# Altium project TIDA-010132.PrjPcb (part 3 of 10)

## Sheet AFE1-LMX2594.SchDoc
size 558 x 431 mm; Date: Not shown in title block; ApprovedBy: Not shown in title block; CheckedBy: Not shown in title block; Author: Not shown in title block; CompanyName: Not shown in title block; DrawnBy: Avinash N; Engineer: Not shown in title block; Organization: Not shown in title block; Address1: Not shown in title block; Address2: Not shown in title block; Address3: Not shown in title block; Address4: Not shown in title block; DocumentNumber: 1; Revision: Use project parameter SCH_Rev; SheetNumber: 5; SheetTotal: 32; PageSetup: Record=PageOptions¦CenterHorizontal=True¦CenterVertical=True¦PrintScale=1.00¦XCorrection=1.00¦YCorrection=1.00¦PrintKind=0¦BorderSize=5000000¦LeftOffset=0¦BottomOffset=0¦Orientation=2¦PaperLength=1000¦PaperWidth=1000¦Scale=100¦PaperSource=15¦PrintQuality=600¦MediaType=1¦DitherType=10¦PaperKind=Letter¦PrintScaleMode=1
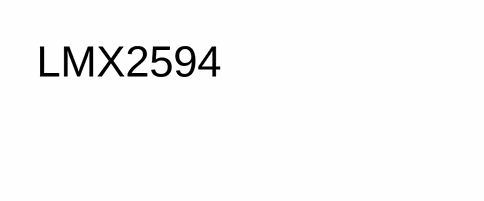
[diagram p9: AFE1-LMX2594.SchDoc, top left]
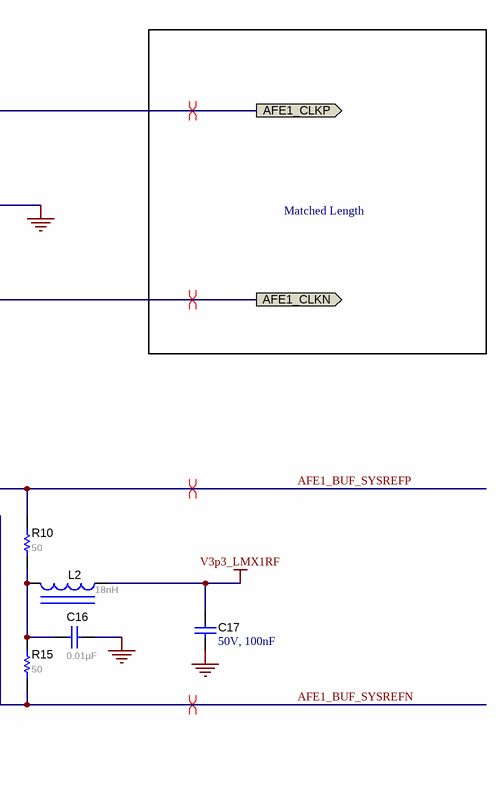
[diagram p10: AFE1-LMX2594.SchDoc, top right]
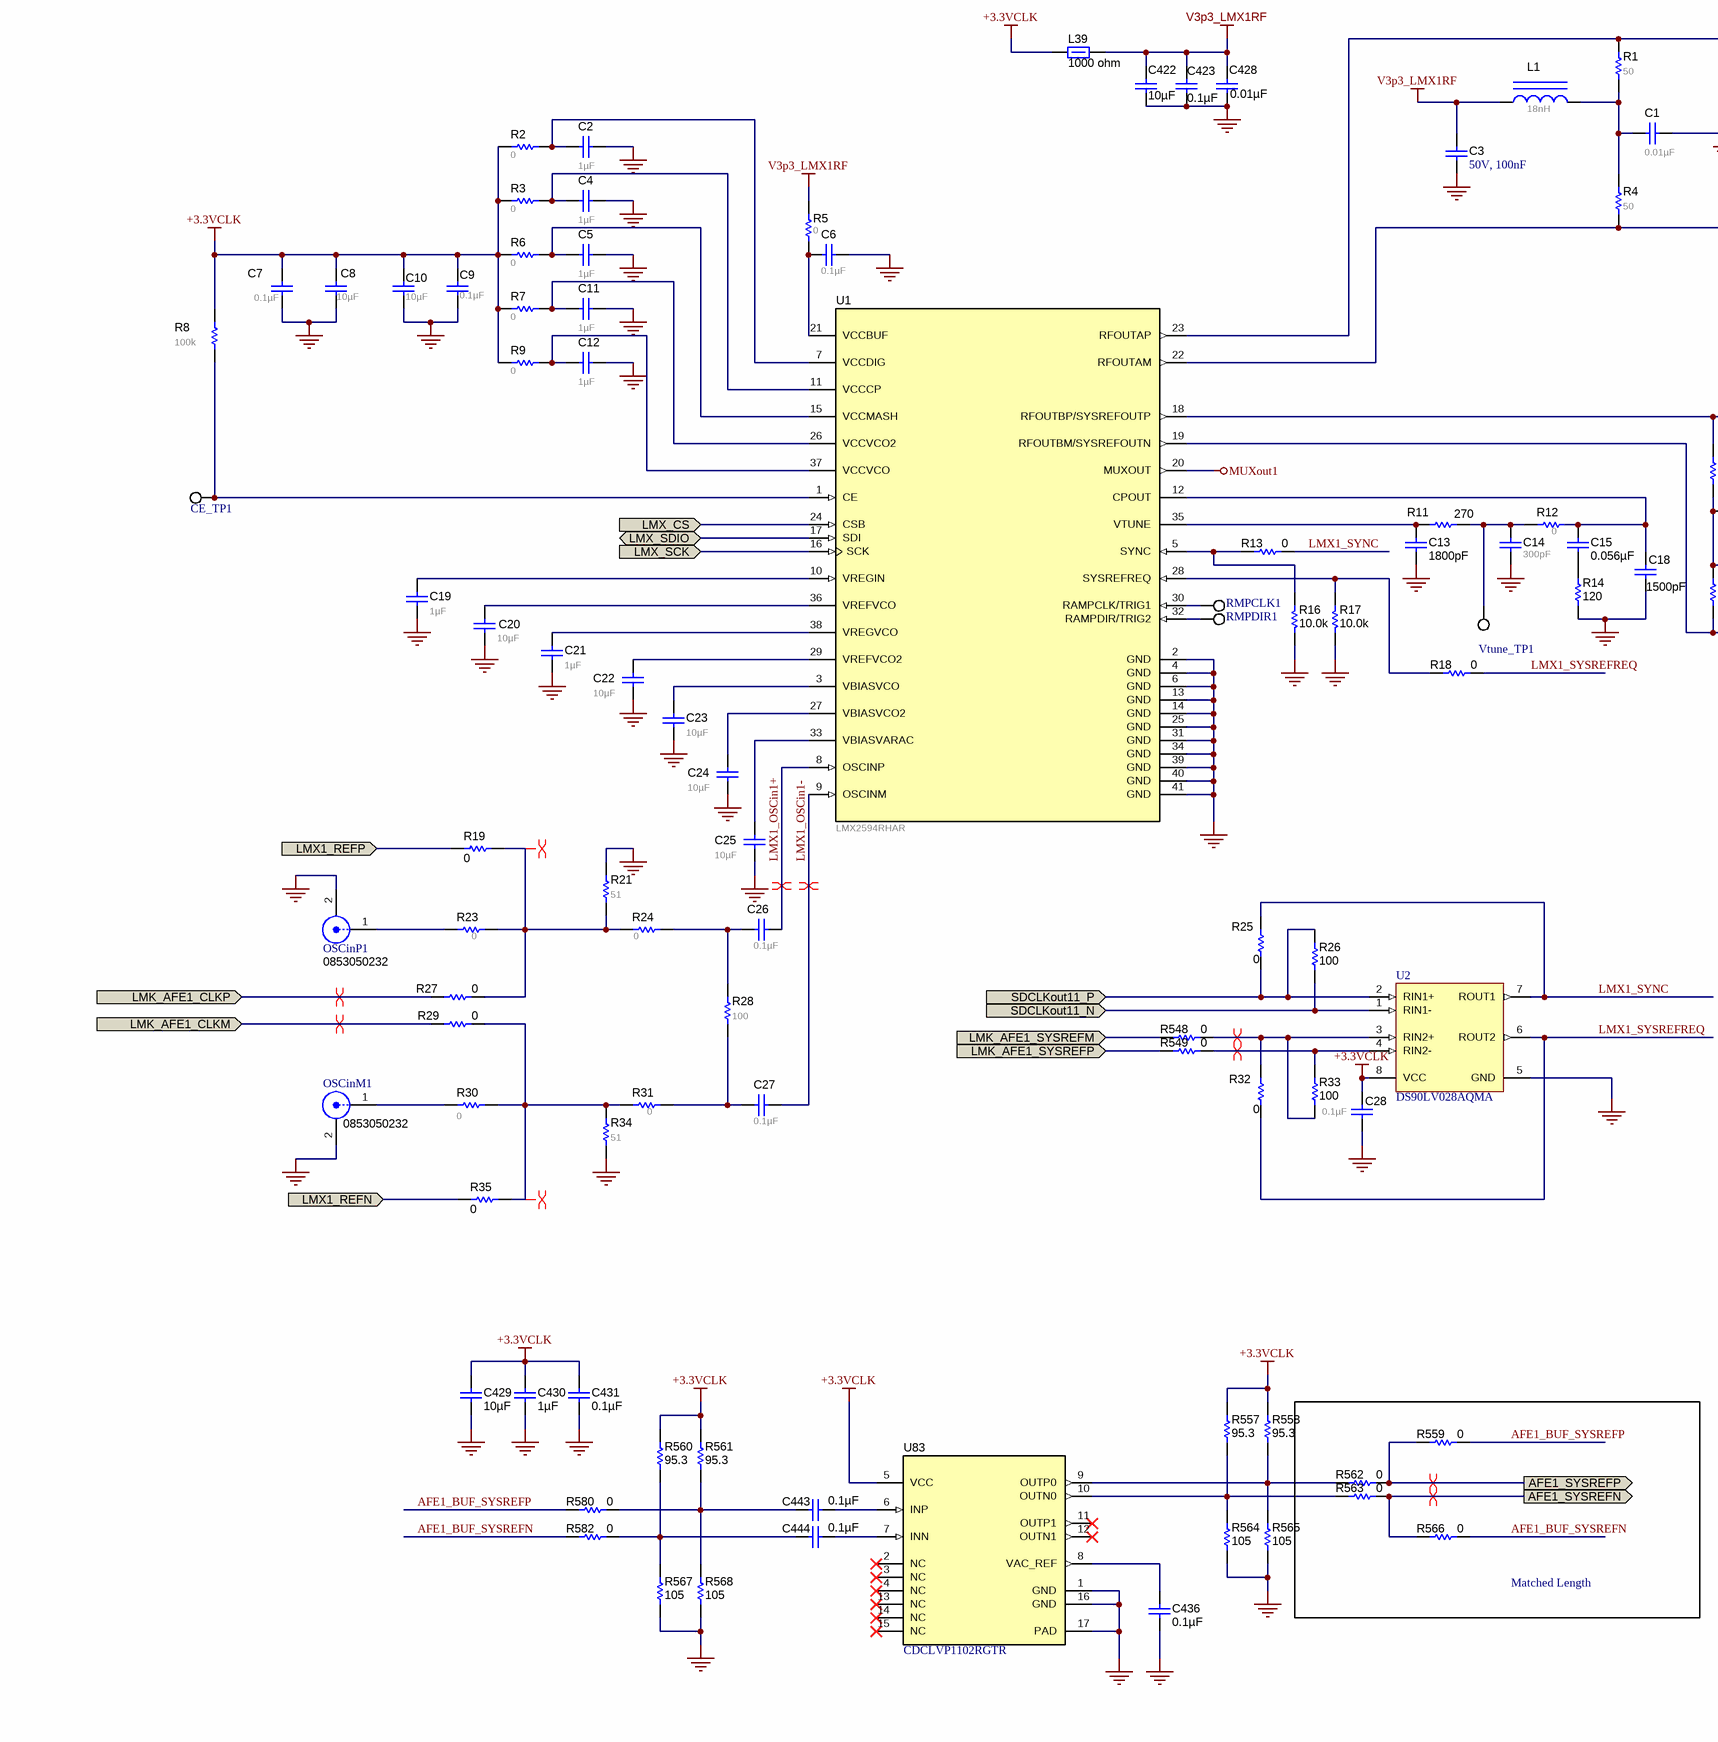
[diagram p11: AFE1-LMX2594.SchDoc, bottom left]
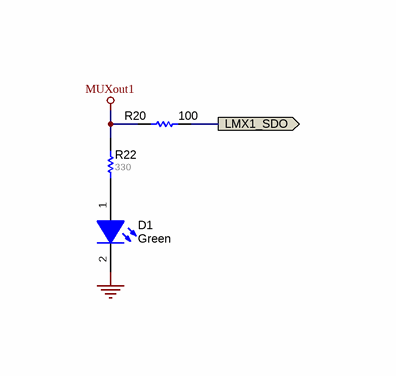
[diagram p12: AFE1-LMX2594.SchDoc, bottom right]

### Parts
C1  ValueDisplayed: 0.01µF  [0402_065]  (hidden comment: 520L103KT16T)
C2  ValueDisplayed: 1µF  [0603]  (hidden comment: C1608X7R1C105K080AC)
C3  50V, 100nF  [0603_1.6x0.8x0.8mm_Reflow Soldering]
C4  ValueDisplayed: 1µF  [0603L]  (hidden comment: C1608X7R1C105K080AC)
C5  ValueDisplayed: 1µF  [0603L]  (hidden comment: C1608X7R1C105K080AC)
C6  ValueDisplayed: 0.1µF  [0603L]  (hidden comment: 0603YC104JAT2A)
C7  ValueDisplayed: 0.1µF  [0603]  (hidden comment: 0603YC104JAT2A)
C8  ValueDisplayed: 10µF  [0805]  (hidden comment: C0805C106K8PACTU)
C9  ValueDisplayed: 0.1µF  [0603]  (hidden comment: 0603YC104JAT2A)
C10  ValueDisplayed: 10µF  [0805]  (hidden comment: C0805C106K8PACTU)
C11  ValueDisplayed: 1µF  [0603]  (hidden comment: C1608X7R1C105K080AC)
C12  ValueDisplayed: 1µF  [0603]  (hidden comment: C1608X7R1C105K080AC)
C13  ValueDisplayed: 1800pF  [0603]  (hidden comment: GRM1885C1H182JA01D)
C14  ValueDisplayed: 300pF  [0603]  (hidden comment: GRM1885C2A301JA01D)
C15  ValueDisplayed: 0.056µF  [0603]  (hidden comment: C0603C563J4RACTU)
C16  ValueDisplayed: 0.01µF  [0402_065]  (hidden comment: 520L103KT16T)
C17  50V, 100nF  [0603_1.6x0.8x0.8mm_Reflow Soldering]
C18  ValueDisplayed: 1500pF  [0603]  (hidden comment: 06031C152JAT2A)
C19  ValueDisplayed: 1µF  [0603]  (hidden comment: C1608X7R1C105K080AC)
C20  ValueDisplayed: 10µF  [0603]  (hidden comment: C1608X5R1A106M080AC)
C21  ValueDisplayed: 1µF  [0603]  (hidden comment: C1608X7R1C105K080AC)
C22  ValueDisplayed: 10µF  [0603]  (hidden comment: C1608X5R1A106M080AC)
C23  ValueDisplayed: 10µF  [0603]  (hidden comment: C1608X5R1A106M080AC)
C24  ValueDisplayed: 10µF  [0603]  (hidden comment: C1608X5R1A106M080AC)
C25  ValueDisplayed: 10µF  [0603]  (hidden comment: C1608X5R1A106M080AC)
C26  ValueDisplayed: 0.1µF  [0603L]  (hidden comment: 0603YC104JAT2A)
C27  ValueDisplayed: 0.1µF  [0603L]  (hidden comment: 0603YC104JAT2A)
C28  ValueDisplayed: 0.1µF  [0603]  (hidden comment: 0603YC104JAT2A)
C422  ValueDisplayed: 10µF  [1206_190]  (hidden comment: C3216X7R1E106M160AE)
C423  ValueDisplayed: 0.1µF  [0603]  (hidden comment: CGA3E2X7R1H104K080AA)
C428  ValueDisplayed: 0.01µF  [0603]  (hidden comment: GCM188R71H103KA37D)
C429  ValueDisplayed: 10µF  [0603]  (hidden comment: EMK107BBJ106MA-T)
C430  ValueDisplayed: 1µF  [0402]  (hidden comment: C1005X7S1A105K050BC)
C431  ValueDisplayed: 0.1µF  [0402]  (hidden comment: GRM155R71C104KA88D)
C436  ValueDisplayed: 0.1µF  [0402]  (hidden comment: GRM155R71C104KA88D)
C443  ValueDisplayed: 0.1µF  [0402]  (hidden comment: C1005X7R1E104M050BB)
C444  ValueDisplayed: 0.1µF  [0402]  (hidden comment: C1005X7R1E104M050BB)
CE_TP1  5002  [Keystone5002]  (value not drawn)
D1  value Green  [LTST-C191_Green]  (hidden comment: LTST-C191TGKT)
L1  ValueDisplayed: 18nH  [IND_LQG15H]  (hidden comment: LQG15HS18NJ02D)
L2  ValueDisplayed: 18nH  [IND_LQG15H]  (hidden comment: LQG15HS18NJ02D)
L39  ValueDisplayed: 1000 ohm  [1806_HighSpeed]  (hidden comment: BLM41PG102SN1L)
OSCinM1  0853050232  [Molex_0853050232]
OSCinP1  0853050232  [Molex_0853050232]
R1  ValueDisplayed: 50  [0402L]  (hidden comment: FC0402E50R0BST1)
R2  value 0  [0603]  (hidden comment: CRCW06030000Z0EA)
R3  value 0  [0603L]  (hidden comment: CRCW06030000Z0EA)
R4  ValueDisplayed: 50  [0402L]  (hidden comment: FC0402E50R0BST1)
R5  value 0  [0603L]  (hidden comment: CRCW06030000Z0EA)
R6  value 0  [0603L]  (hidden comment: CRCW06030000Z0EA)
R7  value 0  [0603]  (hidden comment: CRCW06030000Z0EA)
R8  ValueDisplayed: 100k  [0603]  (hidden comment: CRCW0603100KJNEA)
R9  value 0  [0603]  (hidden comment: CRCW06030000Z0EA)
R10  ValueDisplayed: 50  [0402L]  (hidden comment: FC0402E50R0BST1)
R11  ValueDisplayed: 270  [0603]  (hidden comment: RC0603JR-07270RL)
R12  ValueDisplayed: 0  [0603]  (hidden comment: CRCW06030000Z0EA)
R13  ValueDisplayed: 0  [0402]  (hidden comment: CRCW04020000Z0ED)
R14  ValueDisplayed: 120  [0603]  (hidden comment: RT0603DRE07120RL)
R15  ValueDisplayed: 50  [0402L]  (hidden comment: FC0402E50R0BST1)
R16  ValueDisplayed: 10.0k  [0402]  (hidden comment: CRCW040210K0DHEDP)
R17  ValueDisplayed: 10.0k  [0402]  (hidden comment: CRCW040210K0DHEDP)
R18  ValueDisplayed: 0  [0402]  (hidden comment: CRCW04020000Z0ED)
R19  ValueDisplayed: 0  [0402]  (hidden comment: CRCW04020000Z0ED)
R20  ValueDisplayed: 100  [0603]  (hidden comment: CRCW0603100RFKEA)
R21  ValueDisplayed: 51  [0603]  (hidden comment: CRCW060351R0JNEA)
R22  value 330  [0603]  (hidden comment: RC0603JR-07330RL)
R23  ValueDisplayed: 0  [0603]  (hidden comment: CRCW06030000Z0EA)
R24  ValueDisplayed: 0  [0603]  (hidden comment: CRCW06030000Z0EA)
R25  ValueDisplayed: 0  [0402]  (hidden comment: CRCW04020000Z0ED)
R26  ValueDisplayed: 100  [0402]  (hidden comment: CRCW0402100RJNED)
R27  ValueDisplayed: 0  [0402]  (hidden comment: CRCW04020000Z0ED)
R28  ValueDisplayed: 100  [0603L]  (hidden comment: CRCW0603100RFKEA)
R29  ValueDisplayed: 0  [0402]  (hidden comment: CRCW04020000Z0ED)
R30  ValueDisplayed: 0  [0603]  (hidden comment: CRCW06030000Z0EA)
R31  ValueDisplayed: 0  [0603]  (hidden comment: CRCW06030000Z0EA)
R32  ValueDisplayed: 0  [0402]  (hidden comment: CRCW04020000Z0ED)
R33  ValueDisplayed: 100  [0402]  (hidden comment: CRCW0402100RJNED)
R34  ValueDisplayed: 51  [0603]  (hidden comment: CRCW060351R0JNEA)
R35  ValueDisplayed: 0  [0402]  (hidden comment: CRCW04020000Z0ED)
R548  ValueDisplayed: 0  [0402]  (hidden comment: CRCW04020000Z0ED)
R549  ValueDisplayed: 0  [0402]  (hidden comment: CRCW04020000Z0ED)
R557  ValueDisplayed: 95.3  [0402]  (hidden comment: CRCW040295R3FKED)
R558  ValueDisplayed: 95.3  [0402]  (hidden comment: CRCW040295R3FKED)
R559  ValueDisplayed: 0  [0402]  (hidden comment: CRCW04020000Z0ED)
R560  ValueDisplayed: 95.3  [0402]  (hidden comment: CRCW040295R3FKED)
R561  ValueDisplayed: 95.3  [0402]  (hidden comment: CRCW040295R3FKED)
R562  ValueDisplayed: 0  [0402]  (hidden comment: CRCW04020000Z0ED)
R563  ValueDisplayed: 0  [0402]  (hidden comment: CRCW04020000Z0ED)
R564  ValueDisplayed: 105  [0402]  (hidden comment: CRCW0402105RFKED)
R565  ValueDisplayed: 105  [0402]  (hidden comment: CRCW0402105RFKED)
R566  ValueDisplayed: 0  [0402]  (hidden comment: CRCW04020000Z0ED)
R567  ValueDisplayed: 105  [0402]  (hidden comment: CRCW0402105RFKED)
R568  ValueDisplayed: 105  [0402]  (hidden comment: CRCW0402105RFKED)
R580  ValueDisplayed: 0  [0402]  (hidden comment: CRCW04020000Z0ED)
R582  ValueDisplayed: 0  [0402]  (hidden comment: CRCW04020000Z0ED)
RMPCLK1  5002  [Keystone5002]  (value not drawn)
RMPDIR1  5002  [Keystone5002]  (value not drawn)
U1  LMX2594RHAR  [RHA0040A]
U2  DS90LV028AQMA  [M08A_N]
U83  CDCLVP1102RGTR  [RGT0016B]
Vtune_TP1  5002  [Keystone5002]  (value not drawn)

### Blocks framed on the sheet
Matched Length: R559 R562 R563 R566

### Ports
AFE1_CLKN (out), AFE1_CLKP (out), AFE1_SYSREFN (out), AFE1_SYSREFP (out), LMK_AFE1_CLKM (in), LMK_AFE1_CLKP (in), LMK_AFE1_SYSREFM (in), LMK_AFE1_SYSREFP (in), LMX1_REFN (in), LMX1_REFP (in), LMX1_SDO (out), LMX_CS (in), LMX_SCK (in), LMX_SDIO (bidir), SDCLKout11_N (in), SDCLKout11_P (in)

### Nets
+3.3VCLK: C7.2 C8.2 C9.2 C10.2 C28.2 C429.1 C430.1 C431.1 L39.1 R2.1 R3.1 R6.1 R7.2 R8.1 R9.2 R557.2 R558.2 R560.2 R561.2 U2.8(VCC) U83.5(VCC)
GND: C1.1 C2.1 C3.2 C4.1 C5.2 C6.1 C7.1 C8.1 C9.1 C10.1 C11.1 C12.1 C13.1 C14.2 C16.1 C17.2 C18.2 C19.1 C20.2 C21.1 C22.2 C23.2 C24.1 C25.1 C28.1 C422.1 C423.2 C428.2 C429.2 C430.2 C431.2 C436.2 D1.2(K) OSCinM1.2 OSCinP1.2 R14.2 R16.2 R17.2 R21.2 R34.1 R564.1 R565.1 R567.1 R568.1 U1.2(GND) U1.4(GND) U1.6(GND) U1.13(GND) U1.14(GND) U1.25(GND) U1.31(GND) U1.34(GND) U1.39(GND) U1.40(GND) U1.41(GND) U2.5(GND) U83.1(GND) U83.16(GND) U83.17(PAD)
MUXout1: R20.1 R22.2 U1.20(MUXOUT)
V3p3_LMX1RF: C3.1 C17.1 C422.2 C423.1 C428.1 L1.1 L2.1 L39.2 R5.1
AFE1_BUF_SYSREFN: R15.1 R566.2 R582.1 U1.19(RFOUTBM/SYSREFOUTN)
AFE1_BUF_SYSREFP: R10.2 R559.2 R580.1 U1.18(RFOUTBP/SYSREFOUTP)
AFE1_CLKN: R4.1 U1.22(RFOUTAM) ; port AFE1_CLKN
AFE1_CLKP: R1.1 U1.23(RFOUTAP) ; port AFE1_CLKP
AFE1_SYSREFN: R563.2 R566.1 ; port AFE1_SYSREFN
AFE1_SYSREFP: R559.1 R562.2 ; port AFE1_SYSREFP
LMK_AFE1_CLKM: R29.1 ; port LMK_AFE1_CLKM
LMK_AFE1_CLKP: R27.1 ; port LMK_AFE1_CLKP
LMK_AFE1_SYSREFM: R548.1 ; port LMK_AFE1_SYSREFM
LMK_AFE1_SYSREFP: R549.1 ; port LMK_AFE1_SYSREFP
LMX1_OSCin1+: C26.2 U1.8(OSCINP)
LMX1_OSCin1-: C27.2 U1.9(OSCINM)
LMX1_REFN: R35.1 ; port LMX1_REFN
LMX1_REFP: R19.2 ; port LMX1_REFP
LMX1_SDO: R20.2 ; port LMX1_SDO
LMX1_SYNC: R13.2 R25.1 U2.7(ROUT1)
LMX1_SYSREFREQ: R18.2 R32.2 U2.6(ROUT2)
LMX_CS: U1.24(CSB) ; port LMX_CS
LMX_SCK: U1.16(SCK) ; port LMX_SCK
LMX_SDIO: U1.17(SDI) ; port LMX_SDIO
SDCLKout11_N: R26.1 U2.1(RIN1-) ; port SDCLKout11_N
SDCLKout11_P: R25.2 R26.2 U2.2(RIN1+) ; port SDCLKout11_P
NetC1_2: C1.2 L1.2 R1.2 R4.2
NetC2_2: C2.2 R2.2 U1.7(VCCDIG)
NetC4_2: C4.2 R3.2 U1.11(VCCCP)
NetC5_1: C5.1 R6.2 U1.15(VCCMASH)
NetC6_2: C6.2 R5.2 U1.21(VCCBUF)
NetC11_2: C11.2 R7.1 U1.26(VCCVCO2)
NetC12_2: C12.2 R9.1 U1.37(VCCVCO)
NetC13_2: C13.2 R11.1 U1.35(VTUNE)
NetC14_1: C14.1 R11.2 R12.2 Vtune_TP1.1
NetC15_1: C15.1 C18.1 R12.1 U1.12(CPOUT)
NetC15_2: C15.2 R14.1
NetC16_2: C16.2 L2.2 R10.1 R15.2
NetC19_2: C19.2 U1.10(VREGIN)
NetC20_1: C20.1 U1.36(VREFVCO)
NetC21_2: C21.2 U1.38(VREGVCO)
NetC22_1: C22.1 U1.29(VREFVCO2)
NetC23_1: C23.1 U1.3(VBIASVCO)
NetC24_2: C24.2 U1.27(VBIASVCO2)
NetC25_2: C25.2 U1.33(VBIASVARAC)
NetC26_1: C26.1 R24.2 R28.2
NetC27_1: C27.1 R28.1 R31.1
NetC436_1: C436.1 U83.8(VAC_REF)
NetC443_1: C443.1 R561.1 R568.2 R580.2
NetC443_2: C443.2 U83.6(INP)
NetC444_1: C444.1 R560.1 R567.2 R582.2
NetC444_2: C444.2 U83.7(INN)
NetCE_TP1_1: CE_TP1.1 R8.2 U1.1(CE)
NetD1_1: D1.1(A) R22.1
NetOSCinM1_1: OSCinM1.1 R30.1
NetOSCinP1_1: OSCinP1.1 R23.1
NetR13_1: R13.1 R16.1 U1.5(SYNC)
NetR17_1: R17.1 R18.1 U1.28(SYSREFREQ)
NetR19_1: R19.1 R21.1 R23.2 R24.1 R27.2
NetR29_2: R29.2 R30.2 R31.2 R34.2 R35.2
NetR32_1: R32.1 R33.1 R548.2 U2.3(RIN2+)
NetR33_2: R33.2 R549.2 U2.4(RIN2-)
NetR557_1: R557.1 R563.1 R564.2 U83.10(OUTN0)
NetR558_1: R558.1 R562.1 R565.2 U83.9(OUTP0)
NetRMPCLK1_1: RMPCLK1.1 U1.30(RAMPCLK/TRIG1)
NetRMPDIR1_1: RMPDIR1.1 U1.32(RAMPDIR/TRIG2)

Not connected (* = marked no-connect by the designer): U83 2(NC)* 3(NC)* 4(NC)* 11(OUTP1)* 12(OUTN1)* 13(NC)* 14(NC)* 15(NC)*

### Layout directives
differential pair: AFE1_BUF_SYSREFN, AFE1_BUF_SYSREFP, AFE1_CLKN, AFE1_CLKP, AFE1_SYSREFN, AFE1_SYSREFP, LMK_AFE1_CLKM, LMK_AFE1_CLKP, LMX1_OSCin1+, LMX1_OSCin1-, NetR19_1, NetR29_2, NetR32_1, NetR33_2

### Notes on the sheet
- LMX2594
- Matched Length

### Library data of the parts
C1 C16 = 520L103KT16T: CAP, CERM, 0.01 µF, 16 V, +/- 10%, X7R, 0402; Manufacturer: AT Ceramics; Polarized: N; CompType: Capacitor; Value: 0.01uF; U/M: EA; Cap_F: 0.00000001; Tolerance_%: 10; Value1: Unknown; VDC_V: 16; Value2: 16V; TaMin_C: -55; TaMax_C: 125; Cap_Case: 0402; AEC Category: Q200; SizeArea_mm2: 0.5; SizeAreaWB_mm2: 3; SizeX_mm: 1; SizeZ_mm: 0.65
C2 C11 C12 = C1608X7R1C105K080AC: CAP, CERM, 1 µF, 16 V, +/- 10%, X7R, 0603; Manufacturer: TDK; ESR_ohm: 0.0057; Polarized: N; TaMax_C: 125; TaMin_C: -55; Tolerance_%: 10; VDC_V: 16; Cap_F: 0.000001; CompType: Capacitor; Value: 1uF; Value1: 0.0057 ohm; Value2: 16V; U/M: EA; SizeArea_mm2: 1.28; SizeAreaWB_mm2: 4.68; SizeX_mm: 1.6; SizeY_mm: 0.8; SizeZ_mm: 1; AEC Category: Q200
C3 C17 = 885012206095: WCAP-CSGP Ceramic Capacitors, 0603, X7R, 50V, 100nF; Manufacturer: Wurth Electronics Inc.; Rated Voltage: 50V DC
C4 C5 = C1608X7R1C105K080AC: CAP, CERM, 1 µF, 16 V, +/- 10%, X7R, 0603; Manufacturer: TDK; Cap_Case: 0603; ESR_ohm: 0.0057; Polarized: N; TaMax_C: 125; TaMin_C: -55; Tolerance_%: 10; VDC_V: 16; Cap_F: 0.000001; CompType: Capacitor; Value: 1uF; Value1: 0.0057 ohm; Value2: 16V; U/M: EA; SizeArea_mm2: 1.28; SizeAreaWB_mm2: 4.68; SizeX_mm: 1.6; SizeY_mm: 0.8; SizeZ_mm: 1; AEC Category: Q200
C6 C26 C27 = 0603YC104JAT2A: CAP, CERM, 0.1uF, 16V, +/-5%, X7R, 0603; Manufacturer: AVX; Cap_Case: 0603; ESR_Ohm: 0.039; Polarized: N; TaMax_C: 125; TaMin_C: -55; Tolerance_%: 5; VDC_V: 16; Cap_F: 0.0000001; CompType: Capacitor; Value1: 0.039 ohm; U/M: EA
C7 C9 C28 = 0603YC104JAT2A: CAP, CERM, 0.1uF, 16V, +/-5%, X7R, 0603; Manufacturer: AVX; ESR_Ohm: 0.039; Polarized: N; TaMax_C: 125; TaMin_C: -55; Tolerance_%: 5; VDC_V: 16; Cap_F: 0.0000001; CompType: Capacitor; Value1: 0.039 ohm; U/M: EA
C8 C10 = C0805C106K8PACTU: CAP, CERM, 10uF, 10V, +/-10%, X5R, 0805; Manufacturer: Kemet; ESR_Ohm: 0.003; IRMS_A: 11.43; Polarized: N; TaMax_C: 85; TaMin_C: -55; Tolerance_%: 10; Cap_F: 0.00001; CompType: Capacitor; U/M: EA; Value1: 0.003 ohm
C13 = GRM1885C1H182JA01D: CAP, CERM, 1800 pF, 50 V, +/- 5%, C0G/NP0, 0603; Manufacturer: MuRata; Polarized: N; TaMax_C: 125; TaMin_C: -55; Tolerance_%: 5; VDC_V: 50; Cap_F: 0.0000000018; CompType: Capacitor; Value: 1800pF; Value1: Unknown; Value2: 50V; U/M: EA; SizeArea_mm2: 1.28; SizeAreaWB_mm2: 4.68; SizeX_mm: 1.6; SizeY_mm: 0.8; SizeZ_mm: 1; AEC Category: Q200
C14 = GRM1885C2A301JA01D: CAP, CERM, 300pF, 100V, +/-5%, C0G/NP0, 0603; Manufacturer: MuRata; Polarized: N; TaMax_C: 125; TaMin_C: -55; Tolerance_%: 5; VDC_V: 100; Cap_F: 0.0000000003; CompType: Capacitor; Value1: Unknown; U/M: EA
C15 = C0603C563J4RACTU: CAP, CERM, 0.056 µF, 16 V, +/- 5%, X7R, 0603; Manufacturer: Kemet; Polarized: N; TaMax_C: 125; TaMin_C: -55; Tolerance_%: 5; VDC_V: 16; Cap_F: 0.000000056; CompType: Capacitor; Value: 0.056uF; Value1: Unknown; Value2: 16V; U/M: EA; AEC Category: Q200; SizeArea_mm2: 1.28; SizeAreaWB_mm2: 4.68; SizeX_mm: 1.6; SizeY_mm: 0.8; SizeZ_mm: 1
C18 = 06031C152JAT2A: CAP, CERM, 1500 pF, 100 V, +/- 5%, X7R, 0603; Manufacturer: AVX; ESR_ohm: 0.229; Polarized: N; TaMax_C: 125; TaMin_C: -55; Tolerance_%: 5; VDC_V: 100; Cap_F: 0.0000000015; CompType: Capacitor; Value: 1500pF; Value1: 0.229 ohm; Value2: 100V; U/M: EA; AEC Category: Q200; SizeArea_mm2: 1.28; SizeAreaWB_mm2: 4.68; SizeX_mm: 1.6; SizeY_mm: 0.8; SizeZ_mm: 1
C19 = C1608X7R1C105K080AC: CAP, CERM, 1 µF, 16 V, +/- 10%, X7R, 0603; Manufacturer: TDK; Polarized: N; CompType: Capacitor; Value: 1uF; U/M: EA; Cap_F: 0.000001; Tolerance_%: 10; ESR_ohm: 0.0057; Value1: 0.0057 ohm; VDC_V: 16; Value2: 16V; TaMin_C: -55; TaMax_C: 125; AEC Category: Q200
C20 C22-C25 = C1608X5R1A106M080AC: CAP, CERM, 10 µF, 10 V, +/- 20%, X5R, 0603; Manufacturer: TDK; ESR_ohm: 0.0078; IRMS_A: 1.85; Polarized: N; TaMax_C: 85; TaMin_C: -55; Tolerance_%: 20; VDC_V: 10; Cap_F: 0.00001; CompType: Capacitor; Value: 10uF; U/M: EA; Value1: 0.0078 ohm; Value2: 10V; AEC Category: Q200
C21 = C1608X7R1C105K080AC: CAP, CERM, 1 µF, 16 V, +/- 10%, X7R, 0603; Manufacturer: TDK; ESR_ohm: 0.0057; Polarized: N; TaMax_C: 125; TaMin_C: -55; Tolerance_%: 10; VDC_V: 16; Cap_F: 0.000001; CompType: Capacitor; Value: 1uF; U/M: EA; Value1: 0.0057 ohm; Value2: 16V; AEC Category: Q200
C422 = C3216X7R1E106M160AE: CAP, CERM, 10 µF, 25 V, +/- 20%, X7R, 1206_190; Manufacturer: TDK; Polarized: N; CompType: Capacitor; Value: 10uF; U/M: EA; Cap_F: 0.00001; Tolerance_%: 20; Value1: Unknown; VDC_V: 25; Value2: 25V; TaMin_C: -55; TaMax_C: 125; Cap_Case: 1206; SizeArea_mm2: 5.12; SizeAreaWB_mm2: 10.92; SizeX_mm: 3.2; SizeY_mm: 1.6; SizeZ_mm: 1.9; AEC Category: Q200
C423 = CGA3E2X7R1H104K080AA: CAP, CERM, 0.1 µF, 50 V, +/- 10%, X7R, AEC-Q200 Grade 1, 0603; Manufacturer: TDK; Polarized: N; CompType: Capacitor; Value: 0.1uF; U/M: EA; Cap_F: 0.0000001; Tolerance_%: 10; ESR_ohm: 0.0296; Value1: 0.0296 ohm; VDC_V: 50; Value2: 50V; IRMS_A: 0.97199; TaMin_C: -55; TaMax_C: 125; SizeArea_mm2: 1.28; SizeAreaWB_mm2: 4.68; SizeX_mm: 1.6; SizeY_mm: 0.8; SizeZ_mm: 1; AEC Category: Q200; AEC Qualified: Y
C428 = GCM188R71H103KA37D: CAP, CERM, 0.01 µF, 50 V, +/- 10%, X7R, AEC-Q200 Grade 1, 0603; Manufacturer: MuRata; Polarized: N; CompType: Capacitor; Value: 0.01uF; U/M: EA; Cap_F: 0.00000001; Tolerance_%: 10; Value1: Unknown; VDC_V: 50; Value2: 50V; TaMin_C: -55; TaMax_C: 125; SizeArea_mm2: 1.28; SizeAreaWB_mm2: 4.68; SizeX_mm: 1.6; SizeY_mm: 0.8; SizeZ_mm: 1; AEC Category: Q200; AEC Qualified: Y
C429 = EMK107BBJ106MA-T: CAP, CERM, 10 µF, 16 V, +/- 20%, X5R, 0603; Manufacturer: Taiyo Yuden; Polarized: N; CompType: Capacitor; Value: 10uF; U/M: EA; Cap_F: 0.00001; Tolerance_%: 20; Value1: Unknown; VDC_V: 16; Value2: 16V; TaMin_C: -55; TaMax_C: 85; SizeArea_mm2: 1.28; SizeAreaWB_mm2: 4.68; SizeX_mm: 1.6; SizeY_mm: 0.8; SizeZ_mm: 1; AEC Category: Q200
C430 = C1005X7S1A105K050BC: CAP, CERM, 1 µF, 10 V, +/- 10%, X7S, 0402; Manufacturer: TDK; Polarized: N; CompType: Capacitor; Value: 1uF; U/M: EA; Cap_F: 0.000001; Tolerance_%: 10; ESR_ohm: 0.011416; Value1: 0.011416 ohm; Value2: 10V; IRMS_A: 1.483; TaMin_C: -55; TaMax_C: 125; SizeArea_mm2: 0.5; SizeAreaWB_mm2: 3; SizeX_mm: 1; SizeZ_mm: 0.6; AEC Category: Q200
C431 C436 = GRM155R71C104KA88D: CAP, CERM, 0.1 µF, 16 V, +/- 10%, X7R, 0402; Manufacturer: MuRata; Polarized: N; CompType: Capacitor; Value: 0.1uF; U/M: EA; Cap_F: 0.0000001; Tolerance_%: 10; Value1: Unknown; VDC_V: 16; Value2: 16V; TaMin_C: -55; TaMax_C: 125; SizeArea_mm2: 0.5; SizeAreaWB_mm2: 3; SizeX_mm: 1; SizeZ_mm: 0.6; AEC Category: Q200
C443 C444 = C1005X7R1E104M050BB: CAP, CERM, 0.1 µF, 25 V, +/- 20%, X7R, 0402; Manufacturer: TDK; Polarized: N; TaMax_C: 125; TaMin_C: -55; Tolerance_%: 20; VDC_V: 25; Cap_F: 0.0000001; CompType: Capacitor; Value: 0.1uF; Value1: Unknown; Value2: 25V; U/M: EA; SizeArea_mm2: 0.5; SizeAreaWB_mm2: 3; SizeX_mm: 1; SizeZ_mm: 0.6; AEC Category: Q200
CE_TP1 RMPCLK1 RMPDIR1 Vtune_TP1 = 5002: Test Point, Miniature, White, TH; Manufacturer: Keystone; CompType: Test Point Loop; ContactFinish: Silver; Green_Lifecycle: Active; Green_REACh: Passed
D1 = LTST-C191TGKT: LED, Green, SMD; Manufacturer: Lite-On; Type: InGaN; Vf_V: 3.2; Value2: 3.2V; Io_A: 0.02; Value1: W; U/M: EA
L1 L2 = LQG15HS18NJ02D: Inductor, Multilayer, Air Core, 18 nH, 0.3 A, 0.36 ohm, SMD; Manufacturer: MuRata; Value: 18nH; Ind_H: 18.0E-9; Imax_A: 0.3; Irms: 0.3A @ C rise; Isat: 0.3A @ % inductance drop; DCR_ohm: 0.36; Value2: 0.3A; AEC Category: Q200
L39 = BLM41PG102SN1L: Ferrite Bead, 1000 ohm @ 100 MHz, 1.5 A, 1806; Manufacturer: MuRata; Imax_A: 1.5; DCR_ohm: 0.09; Value1: 0.09 ohm; Value2: 1.5A; SizeAreaWB_mm2: 14.3; SizeArea_mm2: 7.2; SizeX_mm: 4.5; SizeY_mm: 1.6; SizeZ_mm: 1.85; ZTyp@100MHz_Ohm: 1000
OSCinM1 OSCinP1 = CMP-0077224-1: Plug, 50 Ohm, Straight, SMT; Manufacturer: Molex; Cert_UL: Y; ContactFinish: Gold; CT: False; Gender: Male; Voltage_V: 335V
R1 R4 R10 R15 = FC0402E50R0BST1: RES, 50, 0.1%, 0.05 W, 0402; Manufacturer: Vishay-Dale; CompType: Resistor; Value: 50; Value_Code: 50R0; Tolerance_%: 0.1; Power_W: 0.05; Value2: 0.05W; TempCo: 25 ppm/C; U/M: EA; SizeArea_mm2: 0.5; SizeX_mm: 1; SizeZ_mm: 0.6; AEC Category: Q200; AEC Qualified: N
R2 R3 R5-R7 R9 = CRCW06030000Z0EA: RES, 0 ohm, 5%, 0.1W, 0603; Manufacturer: Vishay-Dale; CompType: Resistor; Tolerance_%: 5; VDC_V: 75; Power_W: 0.1; U/M: EA; Value_Code: 0000; EIA_Code: E24
R8 = CRCW0603100KJNEA: RES, 100 k, 5%, 0.1 W, 0603; Manufacturer: Vishay-Dale; CompType: Resistor; Tolerance_%: 5; VDC_V: 75; Power_W: 0.1; Res_ohm: 100000; Value: 100k; U/M: EA; Value2: 0.1W; EIA_Code: E24; TempCo: 200 ppm/C; SizeArea_mm2: 1.28; SizeX_mm: 1.6; SizeY_mm: 0.8; SizeZ_mm: 1; AEC Category: Q200
R11 = RC0603JR-07270RL: RES, 270, 5%, 0.1 W, 0603; Manufacturer: Yageo America; CompType: Resistor; Tolerance_%: 5; VDC_V: 50; Power_W: 0.1; Value: 270; U/M: EA; Value_Code: 270R; Value2: 0.1W; EIA_Code: E24; TempCo: 100 ppm/C; SizeArea_mm2: 1.28; SizeX_mm: 1.6; SizeY_mm: 0.8; SizeZ_mm: 1; AEC Category: Q200
R12 R23 R24 R30 R31 = CRCW06030000Z0EA: RES, 0, 5%, 0.1 W, 0603; Manufacturer: Vishay-Dale; CompType: Resistor; Tolerance_%: 5; VDC_V: 75; Power_W: 0.1; Value: 0; U/M: EA; Value_Code: 0000; Value2: 0.1W; EIA_Code: E24; TempCo: 200 ppm/C; SizeArea_mm2: 1.28; SizeX_mm: 1.6; SizeY_mm: 0.8; SizeZ_mm: 1; AEC Category: Q200
R13 R18 R25 R27 R29 R32 R548 R549 R559 R562 R563 R566 R580 R582 = CRCW04020000Z0ED: RES, 0, 5%, 0.063 W, 0402; Manufacturer: Vishay-Dale; CompType: Resistor; Value: 0; Value_Code: 0000; Tolerance_%: 5; Power_W: 0.063; Value2: 0.063W; VDC_V: 50; TempCo: 200 ppm/C; SizeArea_mm2: 0.5; SizeX_mm: 1; SizeZ_mm: 0.6; EIA_Code: E24; U/M: EA; AEC Category: Q200
R14 = RT0603DRE07120RL: RES, 120, 0.5%, 0.1 W, 0603; Manufacturer: Yageo America; CompType: Resistor; Tolerance_%: 0.5; VDC_V: 75; Power_W: 0.1; Value: 120; U/M: EA; Value_Code: 120R; Value2: 0.1W; TempCo: 50 ppm/C; EIA_Code: E192; SizeArea_mm2: 1.28; SizeX_mm: 1.6; SizeY_mm: 0.8; SizeZ_mm: 1; AEC Category: Q200
R16 R17 = CRCW040210K0DHEDP: RES, 10.0 k, 0.5%, 0.063 W, 0402; Manufacturer: Vishay-Dale; CompType: Resistor; Value: 10.0k; Res_ohm: 10000; Value_Code: 10k0; Tolerance_%: 0.5; Power_W: 0.063; Value2: 0.063W; VDC_V: 50; TempCo: 50 ppm/C; SizeX_mm: 1; SizeZ_mm: 0.6; EIA_Code: E192; U/M: EA; AEC Category: Q200
R19 R35 = CRCW04020000Z0ED: RES, 0, 5%, 0.063 W, 0402; Manufacturer: Vishay-Dale; CompType: Resistor; Tolerance_%: 5; VDC_V: 50; Power_W: 0.063; Value: 0; U/M: EA; Value_Code: 0000; Value2: 0.063W; EIA_Code: E24; TempCo: 200 ppm/C; SizeArea_mm2: 0.5; SizeX_mm: 1; SizeZ_mm: 0.6; AEC Category: Q200
R20 = CRCW0603100RFKEA: RES, 100, 1%, 0.1 W, 0603; Manufacturer: Vishay-Dale; CompType: Resistor; Value: 100; Value_Code: 100R; Tolerance_%: 1; Power_W: 0.1; Value2: 0.1W; VDC_V: 75; TempCo: 100 ppm/C; SizeArea_mm2: 1.28; SizeX_mm: 1.6; SizeY_mm: 0.8; EIA_Code: E96; U/M: EA; AEC Category: Q200
R21 R34 = CRCW060351R0JNEA: RES, 51, 5%, 0.1 W, 0603; Manufacturer: Vishay-Dale; CompType: Resistor; Value: 51; Value_Code: 51R0; Tolerance_%: 5; Power_W: 0.1; Value2: 0.1W; VDC_V: 75; TempCo: 200 ppm/C; EIA_Code: E24; U/M: EA; SizeArea_mm2: 1.28; SizeX_mm: 1.6; SizeY_mm: 0.8; SizeZ_mm: 1; AEC Category: Q200
R22 = RC0603JR-07330RL: RES, 330 ohm, 5%, 0.1W, 0603; Manufacturer: Yageo America; CompType: Resistor; Tolerance_%: 5; VDC_V: 50; Power_W: 0.1; U/M: EA; Value_Code: 330R; EIA_Code: E24
R26 R33 = CRCW0402100RJNED: RES, 100, 5%, 0.063 W, 0402; Manufacturer: Vishay-Dale; CompType: Resistor; Value: 100; Value_Code: 100R; Tolerance_%: 5; Power_W: 0.063; Value2: 0.063W; VDC_V: 50; TempCo: 200 ppm/C; SizeArea_mm2: 0.5; SizeX_mm: 1; SizeZ_mm: 0.6; EIA_Code: E24; U/M: EA; AEC Category: Q200
R28 = CRCW0603100RFKEA: RES, 100, 1%, 0.1 W, 0603; Manufacturer: Vishay-Dale; CompType: Resistor; Tolerance_%: 1; VDC_V: 75; Power_W: 0.1; Value: 100; U/M: EA; Value_Code: 100R; Value2: 0.1W; EIA_Code: E96; TempCo: 100 ppm/C; SizeArea_mm2: 1.28; SizeX_mm: 1.6; SizeY_mm: 0.8; AEC Category: Q200
R557 R558 R560 R561 = CRCW040295R3FKED: RES, 95.3, 1%, 0.063 W, 0402; Manufacturer: Vishay-Dale; CompType: Resistor; Value: 95.3; Value_Code: 95R3; Tolerance_%: 1; Power_W: 0.063; Value2: 0.063W; VDC_V: 50; TempCo: 100 ppm/C; SizeArea_mm2: 0.5; SizeZ_mm: 0.6; EIA_Code: E96; U/M: EA; AEC Category: Q200
R564 R565 R567 R568 = CRCW0402105RFKED: RES, 105, 1%, 0.063 W, 0402; Manufacturer: Vishay-Dale; CompType: Resistor; Value: 105; Value_Code: 105R; Tolerance_%: 1; Power_W: 0.063; Value2: 0.063W; VDC_V: 50; TempCo: 100 ppm/C; SizeArea_mm2: 0.5; SizeZ_mm: 0.6; EIA_Code: E96; U/M: EA; AEC Category: Q200
U1 = LMX2594RHAR: High Performance, Wideband PLLatinum RF Synthesizer, RHA0040A (VQFN-40); Alternate PartNumber: LMX2594RHAT; Manufacturer: Texas Instruments; SymbolCreator: Altium; SizeArea_mm2: 36; SizeAreaWB_mm2: 64; SizeX_mm: 6; SizeZ_mm: 1; CompType: IC; U/M: EA
U2 = DS90LV028AQMA: Automotive LVDS Dual Differential Line Receiver, 8-pin Narrow SOIC; Manufacturer: Texas Instruments; PackageTopMarking: NSZXTT*90LV0*28AQM; PowerWise: N; CompType: Interface IC
U83 = CMP-0075857-1: Low Jitter 1:2 Universal-to-LVPECL Buffer, RGT0016B (VQFN-16); Manufacturer: Texas Instruments; Alternate PartNumber: CDCLVP1102RGTT; SizeAreaWB_mm2: 16.0; SizeArea_mm2: 9.0; SizeZ_mm: 1.0; Green_REACh: Passed; SizeY_mm: 3.0; Green_Lifecycle: Active; U/M: EA; CompType: IC

## Sheet AFE1-POWER.SchDoc
size 431 x 279 mm; Date: Not shown in title block; ApprovedBy: Not shown in title block; CheckedBy: Not shown in title block; Author: Not shown in title block; CompanyName: Not shown in title block; DrawnBy: Avinash N; Engineer: Not shown in title block; Organization: Not shown in title block; Address1: Not shown in title block; Address2: Not shown in title block; Address3: Not shown in title block; Address4: Not shown in title block; DocumentNumber: 1; Revision: Use project parameter SCH_Rev; SheetNumber: 13; SheetTotal: 32; PageSetup: Record=PageOptions¦CenterHorizontal=True¦CenterVertical=True¦PrintScale=1.00¦XCorrection=1.00¦YCorrection=1.00¦PrintKind=0¦BorderSize=5000000¦LeftOffset=0¦BottomOffset=0¦Orientation=2¦PaperLength=1000¦PaperWidth=1000¦Scale=100¦PaperSource=15¦PrintQuality=600¦MediaType=1¦DitherType=10¦PaperKind=Letter¦PrintScaleMode=1
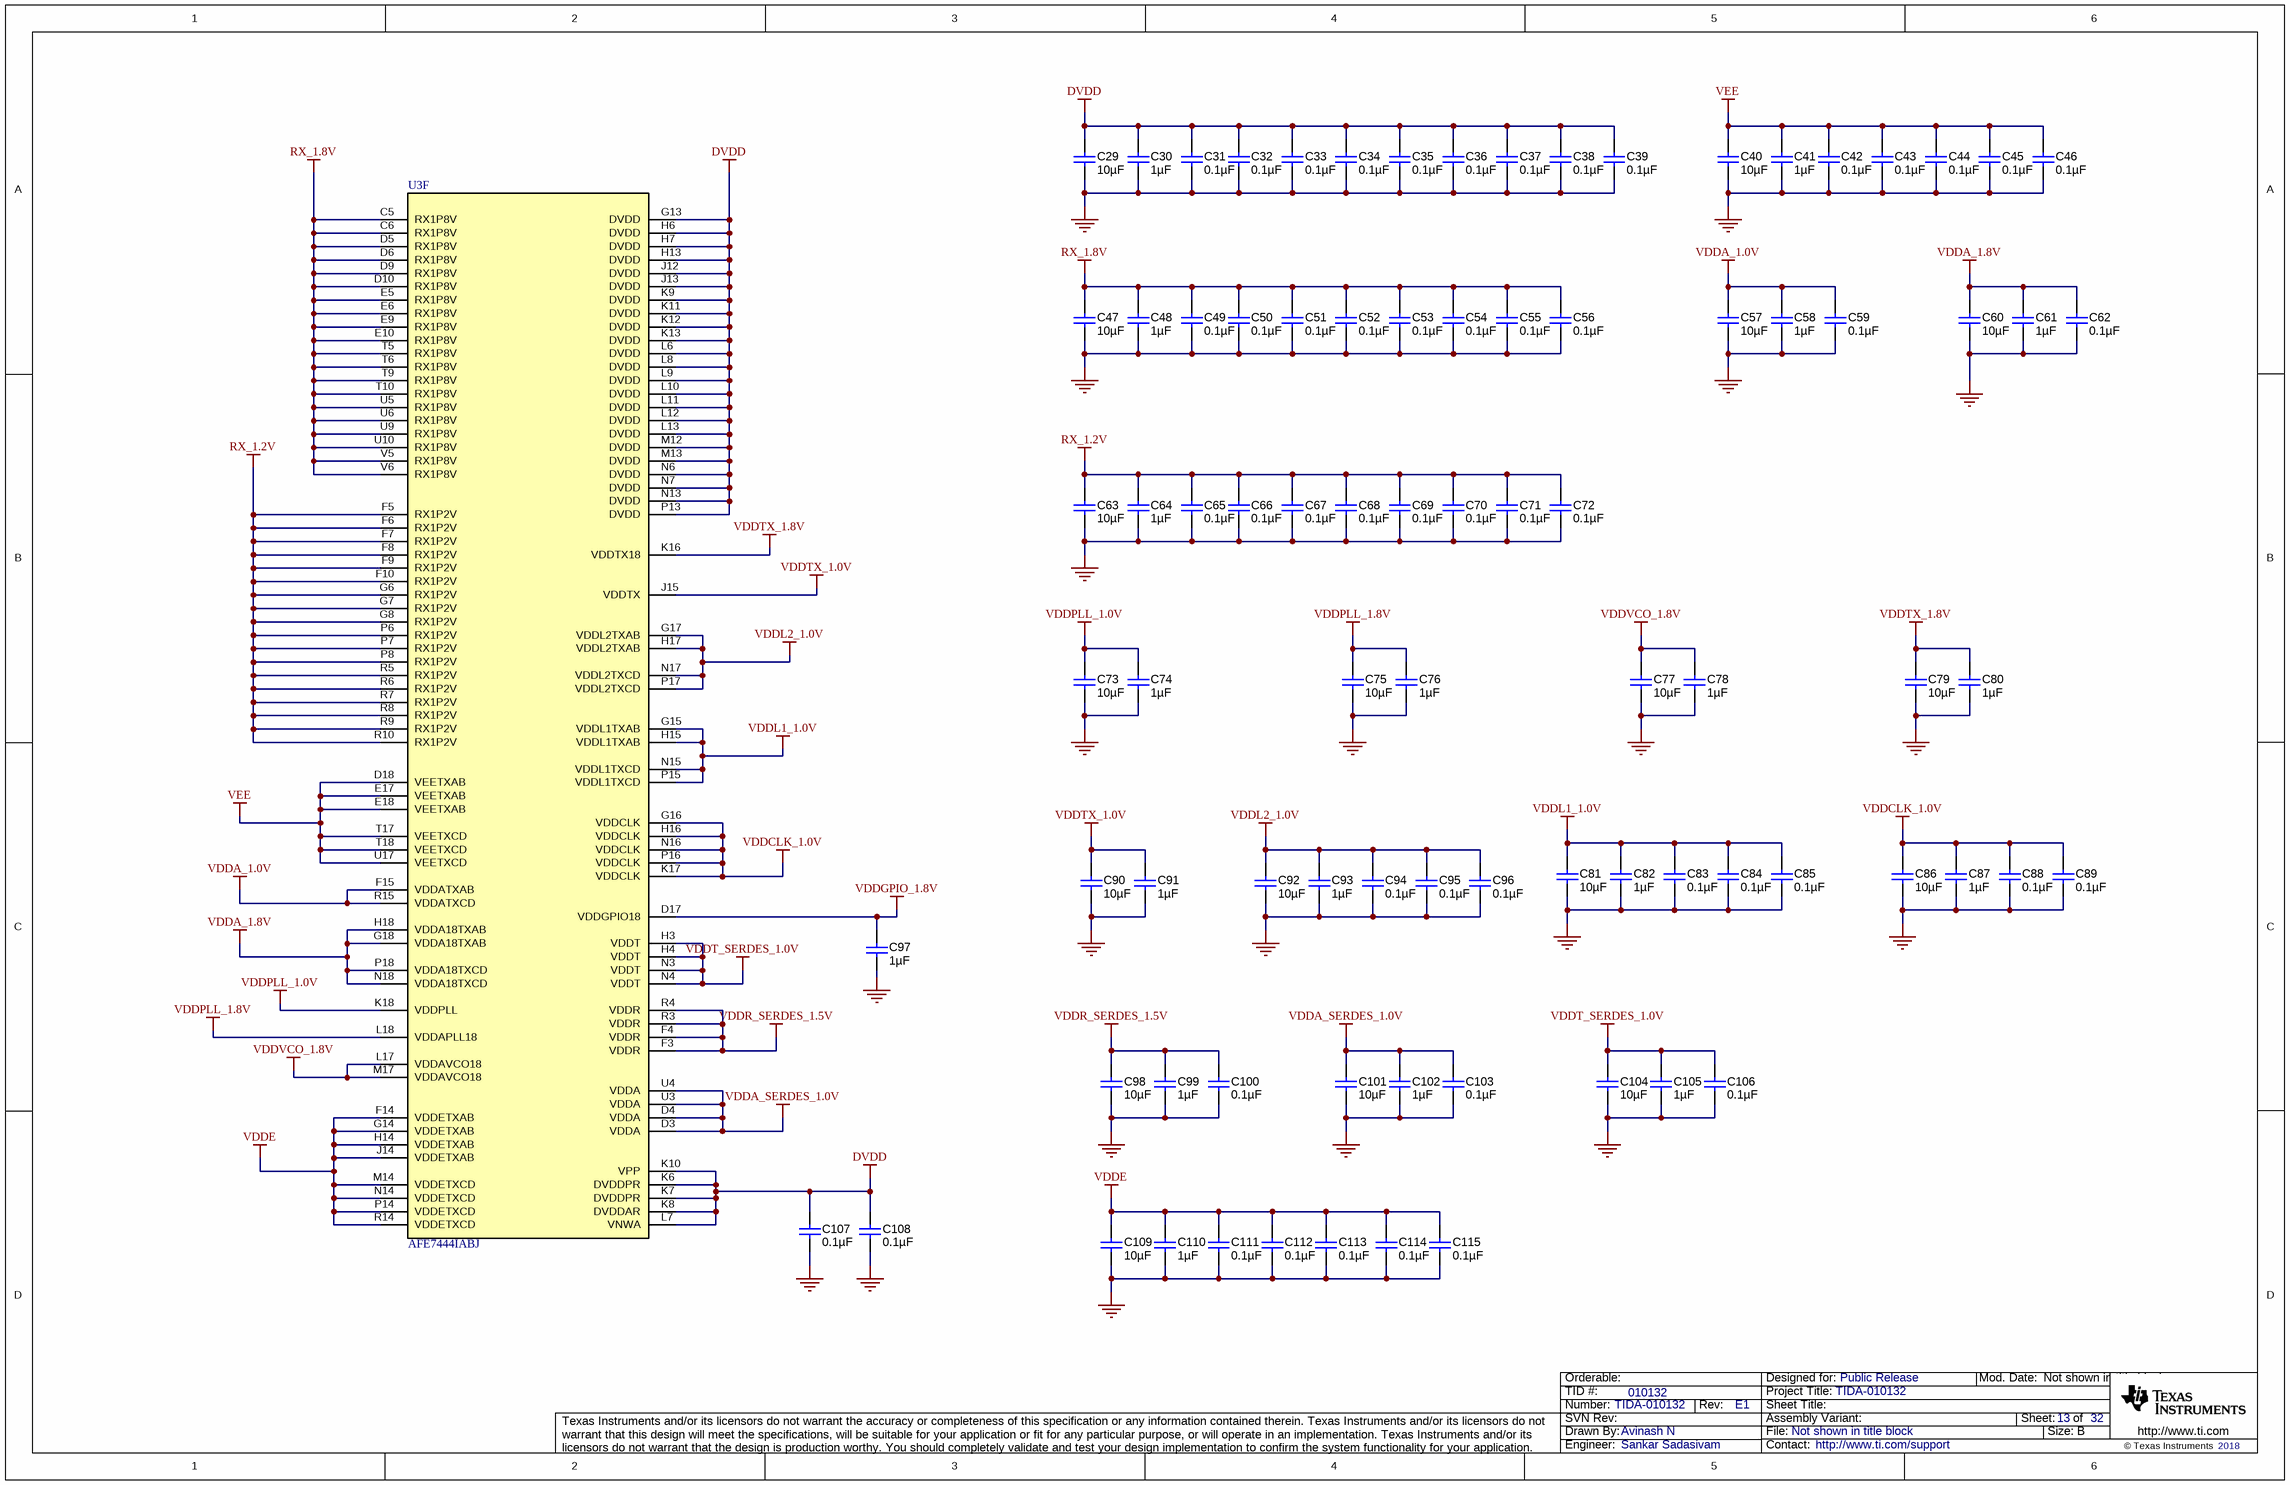
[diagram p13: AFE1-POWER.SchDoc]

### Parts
C29  ValueDisplayed: 10µF  [0402_070]  (hidden comment: GRM155R61A106ME21D)
C30  ValueDisplayed: 1µF  [0201]  (hidden comment: CL03A105MP3NSNC)
C31  ValueDisplayed: 0.1µF  [0201]  (hidden comment: GRM033C71A104KE14D)
C32  ValueDisplayed: 0.1µF  [0201]  (hidden comment: GRM033C71A104KE14D)
C33  ValueDisplayed: 0.1µF  [0201]  (hidden comment: GRM033C71A104KE14D)
C34  ValueDisplayed: 0.1µF  [0201]  (hidden comment: GRM033C71A104KE14D)
C35  ValueDisplayed: 0.1µF  [0201]  (hidden comment: GRM033C71A104KE14D)
C36  ValueDisplayed: 0.1µF  [0201]  (hidden comment: GRM033C71A104KE14D)
C37  ValueDisplayed: 0.1µF  [0201]  (hidden comment: GRM033C71A104KE14D)
C38  ValueDisplayed: 0.1µF  [0201]  (hidden comment: GRM033C71A104KE14D)
C39  ValueDisplayed: 0.1µF  [0201]  (hidden comment: GRM033C71A104KE14D)
C40  ValueDisplayed: 10µF  [0402_070]  (hidden comment: GRM155R61A106ME21D)
C41  ValueDisplayed: 1µF  [0201]  (hidden comment: CL03A105MP3NSNC)
C42  ValueDisplayed: 0.1µF  [0201]  (hidden comment: GRM033C71A104KE14D)
C43  ValueDisplayed: 0.1µF  [0201]  (hidden comment: GRM033C71A104KE14D)
C44  ValueDisplayed: 0.1µF  [0201]  (hidden comment: GRM033C71A104KE14D)
C45  ValueDisplayed: 0.1µF  [0201]  (hidden comment: GRM033C71A104KE14D)
C46  ValueDisplayed: 0.1µF  [0201]  (hidden comment: GRM033C71A104KE14D)
C47  ValueDisplayed: 10µF  [0402_070]  (hidden comment: GRM155R61A106ME21D)
C48  ValueDisplayed: 1µF  [0201]  (hidden comment: CL03A105MP3NSNC)
C49  ValueDisplayed: 0.1µF  [0201]  (hidden comment: GRM033C71A104KE14D)
C50  ValueDisplayed: 0.1µF  [0201]  (hidden comment: GRM033C71A104KE14D)
C51  ValueDisplayed: 0.1µF  [0201]  (hidden comment: GRM033C71A104KE14D)
C52  ValueDisplayed: 0.1µF  [0201]  (hidden comment: GRM033C71A104KE14D)
C53  ValueDisplayed: 0.1µF  [0201]  (hidden comment: GRM033C71A104KE14D)
C54  ValueDisplayed: 0.1µF  [0201]  (hidden comment: GRM033C71A104KE14D)
C55  ValueDisplayed: 0.1µF  [0201]  (hidden comment: GRM033C71A104KE14D)
C56  ValueDisplayed: 0.1µF  [0201]  (hidden comment: GRM033C71A104KE14D)
C57  ValueDisplayed: 10µF  [0402_070]  (hidden comment: GRM155R61A106ME21D)
C58  ValueDisplayed: 1µF  [0201]  (hidden comment: CL03A105MP3NSNC)
C59  ValueDisplayed: 0.1µF  [0201]  (hidden comment: GRM033C71A104KE14D)
C60  ValueDisplayed: 10µF  [0402_070]  (hidden comment: GRM155R61A106ME21D)
C61  ValueDisplayed: 1µF  [0201]  (hidden comment: CL03A105MP3NSNC)
C62  ValueDisplayed: 0.1µF  [0201]  (hidden comment: GRM033C71A104KE14D)
C63  ValueDisplayed: 10µF  [0402_070]  (hidden comment: GRM155R61A106ME21D)
C64  ValueDisplayed: 1µF  [0201]  (hidden comment: CL03A105MP3NSNC)
C65  ValueDisplayed: 0.1µF  [0201]  (hidden comment: GRM033C71A104KE14D)
C66  ValueDisplayed: 0.1µF  [0201]  (hidden comment: GRM033C71A104KE14D)
C67  ValueDisplayed: 0.1µF  [0201]  (hidden comment: GRM033C71A104KE14D)
C68  ValueDisplayed: 0.1µF  [0201]  (hidden comment: GRM033C71A104KE14D)
C69  ValueDisplayed: 0.1µF  [0201]  (hidden comment: GRM033C71A104KE14D)
C70  ValueDisplayed: 0.1µF  [0201]  (hidden comment: GRM033C71A104KE14D)
C71  ValueDisplayed: 0.1µF  [0201]  (hidden comment: GRM033C71A104KE14D)
C72  ValueDisplayed: 0.1µF  [0201]  (hidden comment: GRM033C71A104KE14D)
C73  ValueDisplayed: 10µF  [0402_070]  (hidden comment: GRM155R61A106ME21D)
C74  ValueDisplayed: 1µF  [0201]  (hidden comment: CL03A105MP3NSNC)
C75  ValueDisplayed: 10µF  [0402_070]  (hidden comment: GRM155R61A106ME21D)
C76  ValueDisplayed: 1µF  [0201]  (hidden comment: CL03A105MP3NSNC)
C77  ValueDisplayed: 10µF  [0402_070]  (hidden comment: GRM155R61A106ME21D)
C78  ValueDisplayed: 1µF  [0201]  (hidden comment: CL03A105MP3NSNC)
C79  ValueDisplayed: 10µF  [0402_070]  (hidden comment: GRM155R61A106ME21D)
C80  ValueDisplayed: 1µF  [0201]  (hidden comment: CL03A105MP3NSNC)
C81  ValueDisplayed: 10µF  [0402_070]  (hidden comment: GRM155R61A106ME21D)
C82  ValueDisplayed: 1µF  [0201]  (hidden comment: CL03A105MP3NSNC)
C83  ValueDisplayed: 0.1µF  [0201]  (hidden comment: GRM033C71A104KE14D)
C84  ValueDisplayed: 0.1µF  [0201]  (hidden comment: GRM033C71A104KE14D)
C85  ValueDisplayed: 0.1µF  [0201]  (hidden comment: GRM033C71A104KE14D)
C86  ValueDisplayed: 10µF  [0402_070]  (hidden comment: GRM155R61A106ME21D)
C87  ValueDisplayed: 1µF  [0201]  (hidden comment: CL03A105MP3NSNC)
C88  ValueDisplayed: 0.1µF  [0201]  (hidden comment: GRM033C71A104KE14D)
C89  ValueDisplayed: 0.1µF  [0201]  (hidden comment: GRM033C71A104KE14D)
C90  ValueDisplayed: 10µF  [0402_070]  (hidden comment: GRM155R61A106ME21D)
C91  ValueDisplayed: 1µF  [0201]  (hidden comment: CL03A105MP3NSNC)
C92  ValueDisplayed: 10µF  [0402_070]  (hidden comment: GRM155R61A106ME21D)
C93  ValueDisplayed: 1µF  [0201]  (hidden comment: CL03A105MP3NSNC)
C94  ValueDisplayed: 0.1µF  [0201]  (hidden comment: GRM033C71A104KE14D)
C95  ValueDisplayed: 0.1µF  [0201]  (hidden comment: GRM033C71A104KE14D)
C96  ValueDisplayed: 0.1µF  [0201]  (hidden comment: GRM033C71A104KE14D)
C97  ValueDisplayed: 1µF  [0201]  (hidden comment: CL03A105MP3NSNC)
C98  ValueDisplayed: 10µF  [0402_070]  (hidden comment: GRM155R61A106ME21D)
C99  ValueDisplayed: 1µF  [0201]  (hidden comment: CL03A105MP3NSNC)
C100  ValueDisplayed: 0.1µF  [0201]  (hidden comment: GRM033C71A104KE14D)
C101  ValueDisplayed: 10µF  [0402_070]  (hidden comment: GRM155R61A106ME21D)
C102  ValueDisplayed: 1µF  [0201]  (hidden comment: CL03A105MP3NSNC)
C103  ValueDisplayed: 0.1µF  [0201]  (hidden comment: GRM033C71A104KE14D)
C104  ValueDisplayed: 10µF  [0402_070]  (hidden comment: GRM155R61A106ME21D)
C105  ValueDisplayed: 1µF  [0201]  (hidden comment: CL03A105MP3NSNC)
C106  ValueDisplayed: 0.1µF  [0201]  (hidden comment: GRM033C71A104KE14D)
C107  ValueDisplayed: 0.1µF  [0201]  (hidden comment: GRM033C71A104KE14D)
C108  ValueDisplayed: 0.1µF  [0201]  (hidden comment: GRM033C71A104KE14D)
C109  ValueDisplayed: 10µF  [0402_070]  (hidden comment: GRM155R61A106ME21D)
C110  ValueDisplayed: 1µF  [0201]  (hidden comment: CL03A105MP3NSNC)
C111  ValueDisplayed: 0.1µF  [0201]  (hidden comment: GRM033C71A104KE14D)
C112  ValueDisplayed: 0.1µF  [0201]  (hidden comment: GRM033C71A104KE14D)
C113  ValueDisplayed: 0.1µF  [0201]  (hidden comment: GRM033C71A104KE14D)
C114  ValueDisplayed: 0.1µF  [0201]  (hidden comment: GRM033C71A104KE14D)
C115  ValueDisplayed: 0.1µF  [0201]  (hidden comment: GRM033C71A104KE14D)
U3  AFE7444IABJ  [ABJ0400A]  (part F of 6)

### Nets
DVDD: C29.1 C30.1 C31.1 C32.1 C33.1 C34.1 C35.1 C36.1 C37.1 C38.1 C39.1 C107.1 C108.1 U3.G13(DVDD) U3.H6(DVDD) U3.H7(DVDD) U3.H13(DVDD) U3.J12(DVDD) U3.J13(DVDD) U3.K6(DVDDPR) U3.K7(DVDDPR) U3.K8(DVDDAR) U3.K9(DVDD) U3.K10(VPP) U3.K11(DVDD) U3.K12(DVDD) U3.K13(DVDD) U3.L6(DVDD) U3.L7(VNWA) U3.L8(DVDD) U3.L9(DVDD) U3.L10(DVDD) U3.L11(DVDD) U3.L12(DVDD) U3.L13(DVDD) U3.M12(DVDD) U3.M13(DVDD) U3.N6(DVDD) U3.N7(DVDD) U3.N13(DVDD) U3.P13(DVDD)
GND: C29.2 C30.2 C31.2 C32.2 C33.2 C34.2 C35.2 C36.2 C37.2 C38.2 C39.2 C40.2 C41.2 C42.2 C43.2 C44.2 C45.2 C46.2 C47.2 C48.2 C49.2 C50.2 C51.2 C52.2 C53.2 C54.2 C55.2 C56.2 C57.2 C58.2 C59.2 C60.2 C61.2 C62.2 C63.2 C64.2 C65.2 C66.2 C67.2 C68.2 C69.2 C70.2 C71.2 C72.2 C73.2 C74.2 C75.2 C76.2 C77.2 C78.2 C79.2 C80.2 C81.2 C82.2 C83.2 C84.2 C85.2 C86.2 C87.2 C88.2 C89.2 C90.2 C91.2 C92.2 C93.2 C94.2 C95.2 C96.2 C97.2 C98.2 C99.2 C100.2 C101.2 C102.2 C103.2 C104.2 C105.2 C106.2 C107.2 C108.2 C109.2 C110.2 C111.2 C112.2 C113.2 C114.2 C115.2
RX_1.2V: C63.1 C64.1 C65.1 C66.1 C67.1 C68.1 C69.1 C70.1 C71.1 C72.1 U3.F5(RX1P2V) U3.F6(RX1P2V) U3.F7(RX1P2V) U3.F8(RX1P2V) U3.F9(RX1P2V) U3.F10(RX1P2V) U3.G6(RX1P2V) U3.G7(RX1P2V) U3.G8(RX1P2V) U3.P6(RX1P2V) U3.P7(RX1P2V) U3.P8(RX1P2V) U3.R5(RX1P2V) U3.R6(RX1P2V) U3.R7(RX1P2V) U3.R8(RX1P2V) U3.R9(RX1P2V) U3.R10(RX1P2V)
RX_1.8V: C47.1 C48.1 C49.1 C50.1 C51.1 C52.1 C53.1 C54.1 C55.1 C56.1 U3.C5(RX1P8V) U3.C6(RX1P8V) U3.D5(RX1P8V) U3.D6(RX1P8V) U3.D9(RX1P8V) U3.D10(RX1P8V) U3.E5(RX1P8V) U3.E6(RX1P8V) U3.E9(RX1P8V) U3.E10(RX1P8V) U3.T5(RX1P8V) U3.T6(RX1P8V) U3.T9(RX1P8V) U3.T10(RX1P8V) U3.U5(RX1P8V) U3.U6(RX1P8V) U3.U9(RX1P8V) U3.U10(RX1P8V) U3.V5(RX1P8V) U3.V6(RX1P8V)
VDDA_1.0V: C57.1 C58.1 C59.1 U3.F15(VDDATXAB) U3.R15(VDDATXCD)
VDDA_1.8V: C60.1 C61.1 C62.1 U3.G18(VDDA18TXAB) U3.H18(VDDA18TXAB) U3.N18(VDDA18TXCD) U3.P18(VDDA18TXCD)
VDDA_SERDES_1.0V: C101.1 C102.1 C103.1 U3.D3(VDDA) U3.D4(VDDA) U3.U3(VDDA) U3.U4(VDDA)
VDDCLK_1.0V: C86.1 C87.1 C88.1 C89.1 U3.G16(VDDCLK) U3.H16(VDDCLK) U3.K17(VDDCLK) U3.N16(VDDCLK) U3.P16(VDDCLK)
VDDE: C109.1 C110.1 C111.1 C112.1 C113.1 C114.1 C115.1 U3.F14(VDDETXAB) U3.G14(VDDETXAB) U3.H14(VDDETXAB) U3.J14(VDDETXAB) U3.M14(VDDETXCD) U3.N14(VDDETXCD) U3.P14(VDDETXCD) U3.R14(VDDETXCD)
VDDGPIO_1.8V: C97.1 U3.D17(VDDGPIO18)
VDDL1_1.0V: C81.1 C82.1 C83.1 C84.1 C85.1 U3.G15(VDDL1TXAB) U3.H15(VDDL1TXAB) U3.N15(VDDL1TXCD) U3.P15(VDDL1TXCD)
VDDL2_1.0V: C92.1 C93.1 C94.1 C95.1 C96.1 U3.G17(VDDL2TXAB) U3.H17(VDDL2TXAB) U3.N17(VDDL2TXCD) U3.P17(VDDL2TXCD)
VDDPLL_1.0V: C73.1 C74.1 U3.K18(VDDPLL)
VDDPLL_1.8V: C75.1 C76.1 U3.L18(VDDAPLL18)
VDDR_SERDES_1.5V: C98.1 C99.1 C100.1 U3.F3(VDDR) U3.F4(VDDR) U3.R3(VDDR) U3.R4(VDDR)
VDDT_SERDES_1.0V: C104.1 C105.1 C106.1 U3.H3(VDDT) U3.H4(VDDT) U3.N3(VDDT) U3.N4(VDDT)
VDDTX_1.0V: C90.1 C91.1 U3.J15(VDDTX)
VDDTX_1.8V: C79.1 C80.1 U3.K16(VDDTX18)
VDDVCO_1.8V: C77.1 C78.1 U3.L17(VDDAVCO18) U3.M17(VDDAVCO18)
VEE: C40.1 C41.1 C42.1 C43.1 C44.1 C45.1 C46.1 U3.D18(VEETXAB) U3.E17(VEETXAB) U3.E18(VEETXAB) U3.T17(VEETXCD) U3.T18(VEETXCD) U3.U17(VEETXCD)

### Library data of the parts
C29 C40 C47 C57 C60 C63 C73 C75 C77 C79 C81 C86 C90 C92 C98 C101 C104 C109 = GRM155R61A106ME21D: CAP, CERM, 10 µF, 10 V,+/- 20%, X5R, 0402; Manufacturer: MuRata; Polarized: N; CompType: Capacitor; Value: 10uF; U/M: EA; Cap_F: 0.00001; Tolerance_%: 20; VDC_V: 10; Value2: 10V; TaMin_C: -55; TaMax_C: 85; Cap_Case: 0402; SizeArea_mm2: 0.5; SizeAreaWB_mm2: 3; SizeX_mm: 1; SizeZ_mm: 0.7; AEC Category: Q200; Green_Lifecycle: Not Set; Green_REACh: Incomplete
C30 C41 C48 C58 C61 C64 C74 C76 C78 C80 C82 C87 C91 C93 C97 C99 C102 C105 C110 = CL03A105MP3NSNC: CAP, CERM, 1 µF, 10 V,+/- 20%, X5R, 0201; Manufacturer: Samsung Electro-Mechanics; Polarized: N; CompType: Capacitor; Value: 1uF; U/M: EA; Cap_F: 0.000001; Tolerance_%: 20; VDC_V: 10; Value2: 10V; TaMin_C: -55; TaMax_C: 85; SizeArea_mm2: 0.18; SizeAreaWB_mm2: 2.08; SizeX_mm: 0.6; SizeY_mm: 0.3; SizeZ_mm: 0.26; AEC Category: Q200; Green_Lifecycle: Active; Green_REACh: Passed
C31-C39 C42-C46 C49-C56 C59 C62 C65-C72 C83-C85 C88 C89 C94-C96 C100 C103 C106-C108 C111-C115 = GRM033C71A104KE14D: CAP, CERM, 0.1 µF, 10 V, +/- 10%, X7S, 0201; Manufacturer: MuRata; Polarized: N; CompType: Capacitor; Value: 0.1uF; U/M: EA; Cap_F: 0.0000001; Tolerance_%: 10; Value1: Unknown; Value2: 10V; TaMin_C: -55; TaMax_C: 125; SizeArea_mm2: 0.18; SizeAreaWB_mm2: 2.08; SizeX_mm: 0.6; SizeY_mm: 0.3; SizeZ_mm: 0.26; AEC Category: Q200
U3 = CMP-0084351-1: Quad-Channel RF Sampling Transceiver with 14-bit 9-GSPS DACs and 14-bit 3-GSPS ADCs, ABJ0400A (DSBGA-400); Manufacturer: Texas Instruments; SizeY_mm: 17; AEC Qualified: N; CompType: IC; SizeZ_mm: 2.65; SizeAreaWB_mm2: 361; AEC Category: Q200; SizeArea_mm2: 289

## Sheet AFE1-SERDES.SchDoc
size 431 x 279 mm; Date: Not shown in title block; ApprovedBy: Not shown in title block; CheckedBy: Not shown in title block; Author: Not shown in title block; CompanyName: Not shown in title block; DrawnBy: Avinash N; Engineer: Not shown in title block; Organization: Not shown in title block; Address1: Not shown in title block; Address2: Not shown in title block; Address3: Not shown in title block; Address4: Not shown in title block; DocumentNumber: 1; Revision: Use project parameter SCH_Rev; SheetNumber: 9; SheetTotal: 32; PageSetup: Record=PageOptions¦CenterHorizontal=True¦CenterVertical=True¦PrintScale=1.00¦XCorrection=1.00¦YCorrection=1.00¦PrintKind=0¦BorderSize=5000000¦LeftOffset=0¦BottomOffset=0¦Orientation=2¦PaperLength=1000¦PaperWidth=1000¦Scale=100¦PaperSource=15¦PrintQuality=600¦MediaType=1¦DitherType=10¦PaperKind=Letter¦PrintScaleMode=1
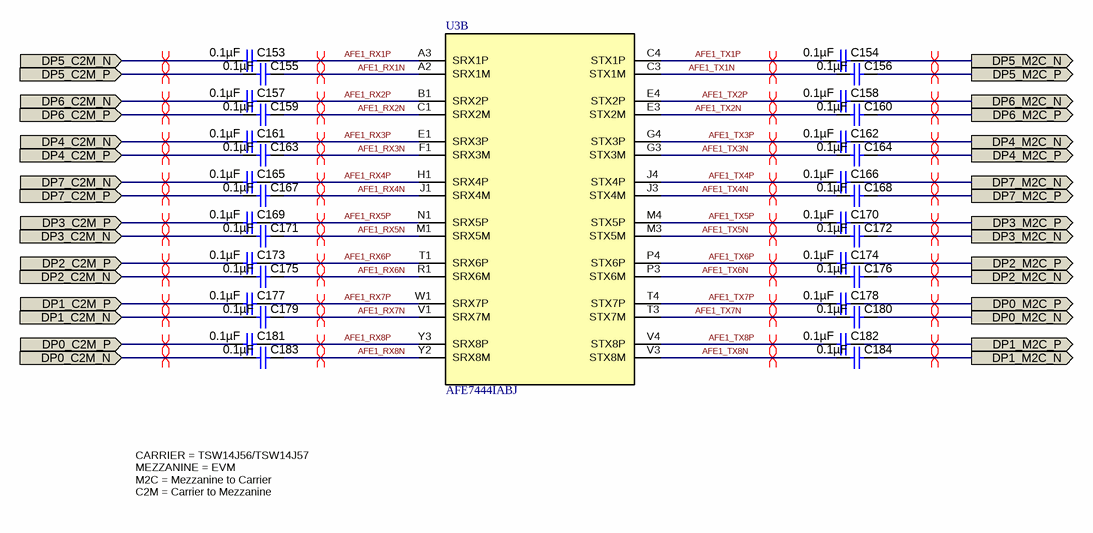
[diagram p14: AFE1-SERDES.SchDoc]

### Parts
C153  ValueDisplayed: 0.1µF  [0201_afe]  (hidden comment: 530Z104KT10T)
C154  ValueDisplayed: 0.1µF  [0201_afe]  (hidden comment: 530Z104KT10T)
C155  ValueDisplayed: 0.1µF  [0201_afe]  (hidden comment: 530Z104KT10T)
C156  ValueDisplayed: 0.1µF  [0201_afe]  (hidden comment: 530Z104KT10T)
C157  ValueDisplayed: 0.1µF  [0201_afe]  (hidden comment: 530Z104KT10T)
C158  ValueDisplayed: 0.1µF  [0201_afe]  (hidden comment: 530Z104KT10T)
C159  ValueDisplayed: 0.1µF  [0201_afe]  (hidden comment: 530Z104KT10T)
C160  ValueDisplayed: 0.1µF  [0201_afe]  (hidden comment: 530Z104KT10T)
C161  ValueDisplayed: 0.1µF  [0201_afe]  (hidden comment: 530Z104KT10T)
C162  ValueDisplayed: 0.1µF  [0201_afe]  (hidden comment: 530Z104KT10T)
C163  ValueDisplayed: 0.1µF  [0201_afe]  (hidden comment: 530Z104KT10T)
C164  ValueDisplayed: 0.1µF  [0201_afe]  (hidden comment: 530Z104KT10T)
C165  ValueDisplayed: 0.1µF  [0201_afe]  (hidden comment: 530Z104KT10T)
C166  ValueDisplayed: 0.1µF  [0201_afe]  (hidden comment: 530Z104KT10T)
C167  ValueDisplayed: 0.1µF  [0201_afe]  (hidden comment: 530Z104KT10T)
C168  ValueDisplayed: 0.1µF  [0201_afe]  (hidden comment: 530Z104KT10T)
C169  ValueDisplayed: 0.1µF  [0201_afe]  (hidden comment: 530Z104KT10T)
C170  ValueDisplayed: 0.1µF  [0201_afe]  (hidden comment: 530Z104KT10T)
C171  ValueDisplayed: 0.1µF  [0201_afe]  (hidden comment: 530Z104KT10T)
C172  ValueDisplayed: 0.1µF  [0201_afe]  (hidden comment: 530Z104KT10T)
C173  ValueDisplayed: 0.1µF  [0201_afe]  (hidden comment: 530Z104KT10T)
C174  ValueDisplayed: 0.1µF  [0201_afe]  (hidden comment: 530Z104KT10T)
C175  ValueDisplayed: 0.1µF  [0201_afe]  (hidden comment: 530Z104KT10T)
C176  ValueDisplayed: 0.1µF  [0201_afe]  (hidden comment: 530Z104KT10T)
C177  ValueDisplayed: 0.1µF  [0201_afe]  (hidden comment: 530Z104KT10T)
C178  ValueDisplayed: 0.1µF  [0201_afe]  (hidden comment: 530Z104KT10T)
C179  ValueDisplayed: 0.1µF  [0201_afe]  (hidden comment: 530Z104KT10T)
C180  ValueDisplayed: 0.1µF  [0201_afe]  (hidden comment: 530Z104KT10T)
C181  ValueDisplayed: 0.1µF  [0201_afe]  (hidden comment: 530Z104KT10T)
C182  ValueDisplayed: 0.1µF  [0201_afe]  (hidden comment: 530Z104KT10T)
C183  ValueDisplayed: 0.1µF  [0201_afe]  (hidden comment: 530Z104KT10T)
C184  ValueDisplayed: 0.1µF  [0201_afe]  (hidden comment: 530Z104KT10T)
U3  AFE7444IABJ  [ABJ0400A]  (part B of 6)

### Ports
DP0_C2M_N (in), DP0_C2M_P (in), DP0_M2C_N (out), DP0_M2C_P (out), DP1_C2M_N (in), DP1_C2M_P (in), DP1_M2C_N (out), DP1_M2C_P (out), DP2_C2M_N (in), DP2_C2M_P (in), DP2_M2C_N (out), DP2_M2C_P (out), DP3_C2M_N (in), DP3_C2M_P (in), DP3_M2C_N (out), DP3_M2C_P (out), DP4_C2M_N (in), DP4_C2M_P (in), DP4_M2C_N (out), DP4_M2C_P (out), DP5_C2M_N (in), DP5_C2M_P (in), DP5_M2C_N (out), DP5_M2C_P (out), DP6_C2M_N (in), DP6_C2M_P (in), DP6_M2C_N (out), DP6_M2C_P (out), DP7_C2M_N (in), DP7_C2M_P (in), DP7_M2C_N (out), DP7_M2C_P (out)

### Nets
AFE1_RX1N: C155.2 U3.A2(SRX1M)
AFE1_RX1P: C153.2 U3.A3(SRX1P)
AFE1_RX2N: C159.2 U3.C1(SRX2M)
AFE1_RX2P: C157.2 U3.B1(SRX2P)
AFE1_RX3N: C163.2 U3.F1(SRX3M)
AFE1_RX3P: C161.2 U3.E1(SRX3P)
AFE1_RX4N: C167.2 U3.J1(SRX4M)
AFE1_RX4P: C165.2 U3.H1(SRX4P)
AFE1_RX5N: C171.2 U3.M1(SRX5M)
AFE1_RX5P: C169.2 U3.N1(SRX5P)
AFE1_RX6N: C175.2 U3.R1(SRX6M)
AFE1_RX6P: C173.2 U3.T1(SRX6P)
AFE1_RX7N: C179.2 U3.V1(SRX7M)
AFE1_RX7P: C177.2 U3.W1(SRX7P)
AFE1_RX8N: C183.2 U3.Y2(SRX8M)
AFE1_RX8P: C181.2 U3.Y3(SRX8P)
AFE1_TX1N: C156.1 U3.C3(STX1M)
AFE1_TX1P: C154.1 U3.C4(STX1P)
AFE1_TX2N: C160.1 U3.E3(STX2M)
AFE1_TX2P: C158.1 U3.E4(STX2P)
AFE1_TX3N: C164.1 U3.G3(STX3M)
AFE1_TX3P: C162.1 U3.G4(STX3P)
AFE1_TX4N: C168.1 U3.J3(STX4M)
AFE1_TX4P: C166.1 U3.J4(STX4P)
AFE1_TX5N: C172.1 U3.M3(STX5M)
AFE1_TX5P: C170.1 U3.M4(STX5P)
AFE1_TX6N: C176.1 U3.P3(STX6M)
AFE1_TX6P: C174.1 U3.P4(STX6P)
AFE1_TX7N: C180.1 U3.T3(STX7M)
AFE1_TX7P: C178.1 U3.T4(STX7P)
AFE1_TX8N: C184.1 U3.V3(STX8M)
AFE1_TX8P: C182.1 U3.V4(STX8P)
DP0_C2M_N: C183.1 ; port DP0_C2M_N
DP0_C2M_P: C181.1 ; port DP0_C2M_P
DP0_M2C_N: C180.2 ; port DP0_M2C_N
DP0_M2C_P: C178.2 ; port DP0_M2C_P
DP1_C2M_N: C179.1 ; port DP1_C2M_N
DP1_C2M_P: C177.1 ; port DP1_C2M_P
DP1_M2C_N: C184.2 ; port DP1_M2C_N
DP1_M2C_P: C182.2 ; port DP1_M2C_P
DP2_C2M_N: C175.1 ; port DP2_C2M_N
DP2_C2M_P: C173.1 ; port DP2_C2M_P
DP2_M2C_N: C176.2 ; port DP2_M2C_N
DP2_M2C_P: C174.2 ; port DP2_M2C_P
DP3_C2M_N: C171.1 ; port DP3_C2M_N
DP3_C2M_P: C169.1 ; port DP3_C2M_P
DP3_M2C_N: C172.2 ; port DP3_M2C_N
DP3_M2C_P: C170.2 ; port DP3_M2C_P
DP4_C2M_N: C161.1 ; port DP4_C2M_N
DP4_C2M_P: C163.1 ; port DP4_C2M_P
DP4_M2C_N: C162.2 ; port DP4_M2C_N
DP4_M2C_P: C164.2 ; port DP4_M2C_P
DP5_C2M_N: C153.1 ; port DP5_C2M_N
DP5_C2M_P: C155.1 ; port DP5_C2M_P
DP5_M2C_N: C154.2 ; port DP5_M2C_N
DP5_M2C_P: C156.2 ; port DP5_M2C_P
DP6_C2M_N: C157.1 ; port DP6_C2M_N
DP6_C2M_P: C159.1 ; port DP6_C2M_P
DP6_M2C_N: C158.2 ; port DP6_M2C_N
DP6_M2C_P: C160.2 ; port DP6_M2C_P
DP7_C2M_N: C165.1 ; port DP7_C2M_N
DP7_C2M_P: C167.1 ; port DP7_C2M_P
DP7_M2C_N: C166.2 ; port DP7_M2C_N
DP7_M2C_P: C168.2 ; port DP7_M2C_P

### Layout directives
differential pair: AFE1_RX1N, AFE1_RX1P, AFE1_RX2N, AFE1_RX2P, AFE1_RX3N, AFE1_RX3P, AFE1_RX4N, AFE1_RX4P, AFE1_RX5N, AFE1_RX5P, AFE1_RX6N, AFE1_RX6P, AFE1_RX7N, AFE1_RX7P, AFE1_RX8N, AFE1_RX8P, AFE1_TX1N, AFE1_TX1P, AFE1_TX2N, AFE1_TX2P, AFE1_TX3N, AFE1_TX3P, AFE1_TX4N, AFE1_TX4P, AFE1_TX5N, AFE1_TX5P, AFE1_TX6N, AFE1_TX6P, AFE1_TX7N, AFE1_TX7P, AFE1_TX8N, AFE1_TX8P, DP0_C2M_N, DP0_C2M_P, DP0_M2C_N, DP0_M2C_P, DP1_C2M_N, DP1_C2M_P, DP1_M2C_N, DP1_M2C_P, DP2_C2M_N, DP2_C2M_P, DP2_M2C_N, DP2_M2C_P, DP3_C2M_N, DP3_C2M_P, DP3_M2C_N, DP3_M2C_P, DP4_C2M_N, DP4_C2M_P, DP4_M2C_N, DP4_M2C_P, DP5_C2M_N, DP5_C2M_P, DP5_M2C_N, DP5_M2C_P, DP6_C2M_N, DP6_C2M_P, DP6_M2C_N, DP6_M2C_P, DP7_C2M_N, DP7_C2M_P, DP7_M2C_N, DP7_M2C_P

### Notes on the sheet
- CARRIER = TSW14J56/TSW14J57
  MEZZANINE = EVM
  M2C = Mezzanine to Carrier
  C2M = Carrier to Mezzanine

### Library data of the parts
C153-C184 = 581-530Z104KTT: Multilayer Ceramic Capacitors MLCC - SMD/SMT 10volts 0.1uF 10%; Manufacturer: ATC; Polarized: N; U/M: EA; Cap_F: 0.0000001; Tolerance_%: 10; Value1: Unknown; Value2: 10V; TempCo: X7S; TaMin_C: -55; TaMax_C: 125; Cap_Case: 0201; SizeArea_mm2: 0.18; SizeAreaWB_mm2: 2.08; SizeX_mm: 0.6; SizeY_mm: 0.3; SizeZ_mm: 0.26; AEC Category: Q200
U3 = CMP-0084351-1: as U3 on sheet AFE1-POWER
